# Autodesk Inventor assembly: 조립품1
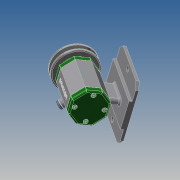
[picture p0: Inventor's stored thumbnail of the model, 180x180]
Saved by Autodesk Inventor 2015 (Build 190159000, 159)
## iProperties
Created: 2018-06
Part Number: 조립품1
Document SubType Name: Assembly
Designer: 김영신
Author: 김영신
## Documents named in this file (16)
- C:\Users\Administrator\Desktop\480608V1015\조립품1.iam
- C:\Users\Administrator\Desktop\480608V1015\본체.ipt
- C:\Users\Administrator\Desktop\480608V1015\앞커버.ipt
- C:\Users\Administrator\Desktop\480608V1015\오일 실 15 25 7.ipt
- C:\Users\Administrator\Desktop\480608V1015\와셔 8x17.ipt
- C:\Users\Administrator\Desktop\480608V1015\축.ipt
- C:\Users\Administrator\Desktop\480608V1015\키 3x3x12.ipt
- 키 3x3x12.ipt
- C:\Users\Administrator\Desktop\480608V1015\V벨트풀리.ipt
- C:\Users\Administrator\Desktop\480608V1015\고무캡.ipt
- C:\Users\Administrator\Desktop\480608V1015\너트 M8.ipt
- 너트 M8.ipt
- C:\Users\Administrator\Desktop\480608V1015\뒤커버.ipt
- C:\Users\Administrator\Desktop\480608V1015\베어링 15x32x9.ipt
- C:\Users\Administrator\Desktop\480608V1015\볼트 M4x12.ipt
- C:\Users\Administrator\Desktop\480608V1015\스프링와셔 8.ipt
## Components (2 placed, 2 different names)
1. V벨트풀리:1 — 각도:2
2. 고무캡:1
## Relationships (1: Angle 1)
- 각도:2 [Angle]: V벨트풀리:1
